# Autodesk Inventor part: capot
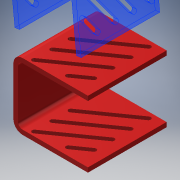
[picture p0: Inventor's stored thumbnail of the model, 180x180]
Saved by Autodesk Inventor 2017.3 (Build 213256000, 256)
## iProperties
Part Number: capot
Material: Plastique PMMA
Document SubType Name: Tôlerie
Designer: ficho
Density: 1.188 g/cm^3
Flat Pattern Width: 5.1852 cm
Flat Pattern Length: 13.1783 cm
Flat Pattern Area: 68.332 cm^2
Sheet Metal Rule: Par défaut_mm
Sheet Metal Width: 51,852 mm
Sheet Metal Length: 131,783 mm
Sheet Metal Area: 6833,196 mm^2
Appearance: Peinture métallisée
Mass: 21.6321 g
Surface Area: 149.433 cm^2
Volume: 18.2088 cm^3
Author: ficho
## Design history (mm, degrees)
node "Face1"
  sketch "Esquisse1"
    geometry: L1 (0, 0)-(49.161, 0); L2 (49.161, 0)-(49.161, 51.852); L3 (49.161, 51.852)-(0, 51.852); L4 (0, 51.852)-(0, 0)
    constraints: 8 end point, 2 parallel, 1 horizontal, 1 perpendicular
    dimensions: "d0" = 49.161 distance between parallel lines of L2 L4; "d1" = 51.852 distance between parallel lines of L1 L3
node "Bord tombé1"
node "Bord tombé2"
sketch "Esquisse5"
  geometry: L1 (8, 48)-(38.15, 26.811); L2 (7.138, 46.773)-(37.288, 25.584); L3 (39.012, 28.038)-(8.862, 49.227); L4 (8, 36)-(38.15, 14.811); L5 (7.138, 34.773)-(37.288, 13.584); L6 (39.012, 16.038)-(8.862, 37.227); L7 (8, 24)-(38.15, 2.811); L8 (7.138, 22.773)-(37.288, 1.584); L9 (39.012, 4.038)-(8.862, 25.227); L10 (0, 0)-(0, 51.852) reference; L11 (46.15, 51.852)-(46.15, 0) reference; L12 (43.15, 0)-(0, 0) reference; L13 (8, 12)-(17.96, 5); L14 (7.138, 10.773)-(17.098, 3.773); L15 (18.823, 6.227)-(8.862, 13.227); A1 r 1.5 centre (8, 48) between (8.862, 49.227) and (7.138, 46.773); A2 r 1.5 centre (38.15, 26.811) between (37.288, 25.584) and (39.012, 28.038); A3 r 1.5 centre (8, 36) between (8.862, 37.227) and (7.138, 34.773); A4 r 1.5 centre (38.15, 14.811) between (37.288, 13.584) and (39.012, 16.038); A5 r 1.5 centre (8, 24) between (8.862, 25.227) and (7.138, 22.773); A6 r 1.5 centre (38.15, 2.811) between (37.288, 1.584) and (39.012, 4.038); A7 r 1.5 centre (8, 12) between (8.862, 13.227) and (7.138, 10.773); A8 r 1.5 centre (17.96, 5) between (17.098, 3.773) and (18.823, 6.227); 5 further points
  constraints: 32 end point, 16 point on circle, 16 tangent, 8 centre point, 6 parallel, 4 midpoint
  dimensions: "d25" = 3 diameter of A2; "d28" = 3 diameter of A4 (= d25); "d29" = 3 diameter of A6 (= d25); "d31" = 8 distance from line of L1.start L10; "d32" = 8 distance from line of L10 L4.start (= d31); "d33" = 8 distance from line of L10 L7.start (= d32); "d34" = 8 distance from line of L11 L1.end (= d31); "d35" = 8 distance from line of L11 L4.end (= d34); "d36" = 8 distance from line of L11 L7.end (= d34); "d37" = 12 distance of L4.start L1.start; "d38" = 12 distance of L7.start L4.start (= d37); "d39" = 24 distance from line of L7.start L12; "d40" = 12 distance of L4.end L1.end (= d37); "d41" = 12 distance of L4.end L7.end (derived); "d42" = 1.5 radius of A8 (= 0.5 x d28); "d43" = 8 distance from line of L10 L13.start (= d31); "d44" = 12 distance of L7.start L13.start (= d37); "d45" = 5 distance from line of L13.end L12
feature "Couper1" sketch "Esquisse5" dims "d26" = 3 (= Epaisseur), "d27" = 0
node "Solide1"
feature "Plaque1" dims "Epaisseur" = 3 (derived)
sketch "Esquisse3"
  geometry: L1 through (25.926, 0) direction (-1, 0); L2 through (0, -21.95) direction (-2.17e-32, -1); L3 (0, -43.9)-(51.852, -43.9); L4 (51.852, -43.9)-(51.852, 0)
  constraints: 6 end point, 1 horizontal, 1 perpendicular, 1 vertical
feature "Plaque2" dims "d5" = 3 (= LargeurGrugeage), "d6" = 1.5 (= ProfondeurGrugeage), "d7" = 6 (= RestesMinimum), "d8" = 3 (= RayonPli), "d9" = 43.9, "d10" = 90 deg, "d11" = 3 (= RayonPli), "d12" = 12 (= TailleGrugeage), "d13" = 3 (= TailleJeu), "d14" = 3 (= TailleRayonJacobi), "Epaisseur" = 3 (derived), "JeuJointure" = 0.01
feature "Pli1" dims "d5" = 3 (= LargeurGrugeage), "d6" = 1.5 (= ProfondeurGrugeage), "d7" = 6 (= RestesMinimum), "d8" = 3 (= RayonPli), "d9" = 43.9, "d10" = 90 deg, "d11" = 3 (= RayonPli), "Epaisseur" = 3 (derived), "JeuJointure" = 0.01
feature "Coin1" dims "d9" = 43.9, "d10" = 90 deg, "d12" = 12 (= TailleGrugeage), "d13" = 3 (= TailleJeu), "d14" = 3 (= TailleRayonJacobi)
sketch "Esquisse4"
  geometry: L1 through (0, -25.926) direction (3.43e-16, 1); L2 through (-24.575, 0) direction (-1, 3.61e-16); L3 (-49.15, 0)-(-49.15, -51.852); L4 (-49.15, -51.852)-(0, -51.852)
  constraints: 6 end point, 1 horizontal, 1 perpendicular, 1 vertical
feature "Plaque3" dims "d15" = 3 (= LargeurGrugeage), "d16" = 1.5 (= ProfondeurGrugeage), "d17" = 6 (= RestesMinimum), "d18" = 3 (= RayonPli), "d19" = 49.15, "d20" = 90 deg, "d21" = 3 (= RayonPli), "d22" = 12 (= TailleGrugeage), "d23" = 3 (= TailleJeu), "d24" = 3 (= TailleRayonJacobi), "Epaisseur" = 3 (derived), "JeuJointure" = 0.01
feature "Pli2" dims "d15" = 3 (= LargeurGrugeage), "d16" = 1.5 (= ProfondeurGrugeage), "d17" = 6 (= RestesMinimum), "d18" = 3 (= RayonPli), "d19" = 49.15, "d20" = 90 deg, "d21" = 3 (= RayonPli), "Epaisseur" = 3 (derived), "JeuJointure" = 0.01
feature "Coin2" dims "d19" = 49.15, "d20" = 90 deg, "d22" = 12 (= TailleGrugeage), "d23" = 3 (= TailleJeu), "d24" = 3 (= TailleRayonJacobi)
feature "Définition1"
other parameters: "FacteurX" = 4.4, "RayonPli" = 3 (= Epaisseur), "LargeurGrugeage" = 3 (= Epaisseur), "ProfondeurGrugeage" = 1.5 (= 0.5 x Epaisseur), "TailleGrugeage" = 12 (= 4 x Epaisseur), "RestesMinimum" = 6 (= 2 x Epaisseur), "Rayondetransition" = 3 (= RayonPli), "TailleRayonJacobi" = 3 (= RayonPli), "TailleJeu" = 3 (= Epaisseur), "d2" = 3 (= RayonPli), "Epaisseur" = 3, "LargeurGrugeage" = 3, "ProfondeurGrugeage" = 1.5, "RayonPli" = 3, "Rayondetransition" = 3, "RestesMinimum" = 6, "TailleGrugeage" = 12, "TailleJeu" = 3, "TailleRayonJacobi" = 3
